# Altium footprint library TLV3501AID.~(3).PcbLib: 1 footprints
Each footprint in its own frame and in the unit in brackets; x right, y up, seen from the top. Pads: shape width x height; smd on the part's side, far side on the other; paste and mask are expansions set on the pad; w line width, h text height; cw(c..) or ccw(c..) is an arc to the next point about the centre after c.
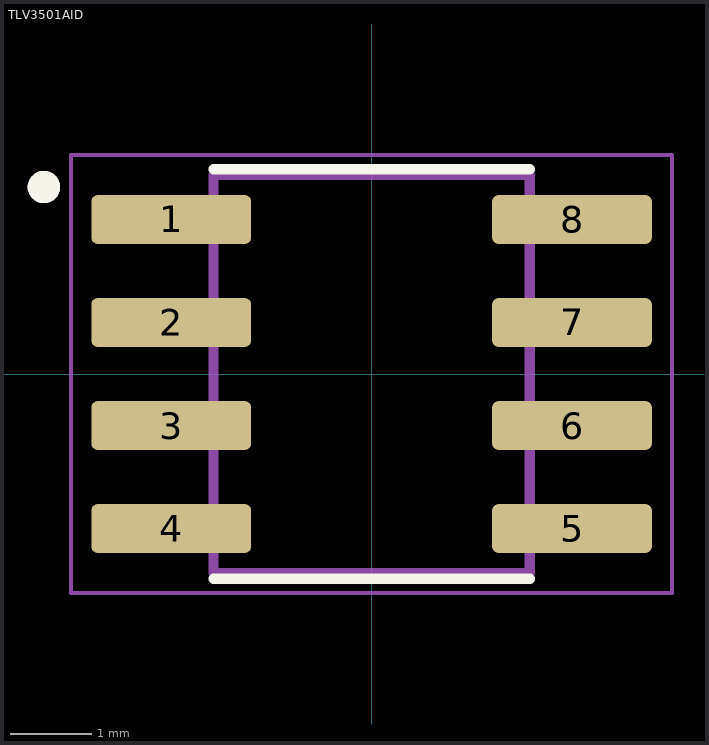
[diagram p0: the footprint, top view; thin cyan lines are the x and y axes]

## TLV3501AID [mm]
pads (8):
  rrect25% 1.97x0.6 smd: 1(-2.47,1.905) 2(-2.47,0.635) 3(-2.47,-0.635) 4(-2.47,-1.905) 5(2.47,-1.905) 6(2.47,-0.635) 7(2.47,0.635) 8(2.47,1.905)
Top Overlay:
  circle w0.2: c-4.04,2.305 r0.1
  lines w0.127: -1.95,-2.525 1.95,-2.525 ; -1.95,2.525 1.95,2.525
Mechanical 13:
  circle w0.2: c-4.04,2.305 r0.1
  lines w0.127: -1.95,-2.452 -1.95,2.452 1.95,2.452 1.95,-2.452 -1.95,-2.452
Mechanical 15:
  lines w0.05: -3.705,-2.702 -3.705,2.702 3.705,2.702 3.705,-2.702 -3.705,-2.702
3D body "TLV3501AID.STEP": height 0, standoff -1.75, extent -3,-2.45 3,2.45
